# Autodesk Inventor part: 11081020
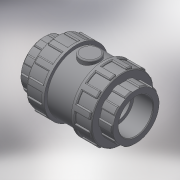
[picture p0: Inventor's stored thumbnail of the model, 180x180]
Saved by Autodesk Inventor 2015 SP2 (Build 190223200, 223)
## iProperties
Created: 2017-11
Part Number: 11081020
Material: Generic
Description: PLASSON CHECK VALVE THR 2" PTFE COATED SPRING + EPDM O-RING
Document SubType Name: Modeling
Designer: KIM
Density: 1 g/cm^3
Appearance: Default
Author: KIM
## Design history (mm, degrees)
derived "110810 - 110610 110910 - 110010.ipt"
feature "Solid1::110810 - 110610 110910 - 110010.ipt"
tag "TaggingFeature1"
body "Solid1"
other parameters: "d0" = 169, "d1" = 56.656, "d2" = 118, "d3" = 38, "d4" = 45.3248, "d5" = 26.6, "d7" = 79.3184, "d8" = 106.2, "d13" = 1.69968, "d23" = 38, "d24" = 113.28, "d25" = 1.13312, "d26" = 1.69968, "d27" = 17.7, "d28" = 8.85, "d29" = 28.5, "d30" = 0, "d35" = 1.69968, "d39" = 59, "d45" = 360 deg, "d47" = 1.13312, "d50" = 59, "d51" = 35.4, "d53" = 0, "d54" = 2.36, "d55" = 11.3312, "d56" = 5.6656, "d58" = 0, "d59" = 1.69968, "d61" = 360 deg, "G_" = 56.656, "l_" = 38, "H_" = 169, "K_" = 118
